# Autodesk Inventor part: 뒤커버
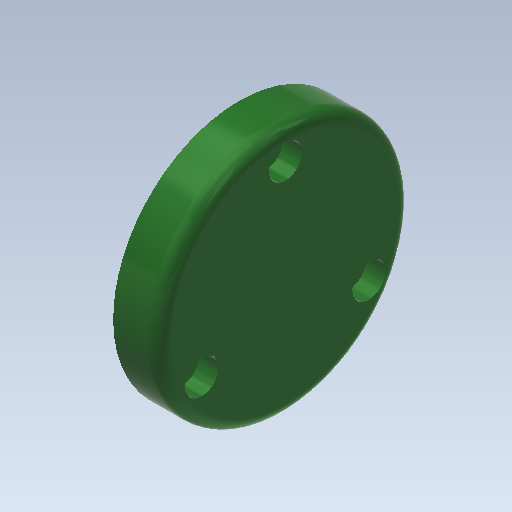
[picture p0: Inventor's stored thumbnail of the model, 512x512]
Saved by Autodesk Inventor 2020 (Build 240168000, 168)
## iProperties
Created: 2015-11
Part Number: 뒤커버
Material: 알루미늄 6061
Document SubType Name: Modeling
Designer: mduedu
Density: 1 g/cm^3
Appearance: 매끄러움 - 짙은 산림 녹색
Author: mduedu
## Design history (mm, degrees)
sketch "스케치5"
  geometry: C1 r 30 at (0, 0); 2 further points
  constraints: 2 coincident, 1 centre point
  dimensions: "d66" = 60 diameter of C1
extrude "돌출2" new body sketch "스케치5" distance "d67" = 11; taper "d68" = 0 deg
sketch "스케치6"
  geometry: C1 r 16 at (0, 0); 1 further point
  constraints: 1 centre point, 1 coincident
  dimensions: "d69" = 32 diameter of C1
extrude "돌출3" join sketch "스케치6" distance "d70" = 3; taper "d71" = 0 deg
hole "구멍5" diameter "d74" = 27; stored, may be unused: countersink angle "d78" = 90 deg, drill point angle "d80" = 0 deg; dims "d75" = 6, "d76" = 4, "d77" = 2, "d79" = 10, "d100" = 10, "d101" = 10
fillet "모깎기8" dims "d82" = 3
fillet "모깎기9" dims "d83" = 3
fillet "모깎기10" dims "d84" = 0.3
sketch "스케치7" dims "d85" = 46
  geometry: 3 further points
  constraints: 2 vertical alignment, 1 coincident, 2 other
hole "구멍6" sketch "스케치7" at (0, 23) diameter "d86" = 4.5; stored, may be unused: countersink angle "d90" = 90 deg, drill point angle "d92" = 0 deg; dims "d87" = 6, "d88" = 8, "d89" = 4.6, "d91" = 10
node "솔리드2"
pattern_circular "원형 패턴3" dims angle "d94" = 360 deg
